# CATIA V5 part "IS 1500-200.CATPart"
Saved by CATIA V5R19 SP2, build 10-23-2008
Part number: IS 1500-200
Bounding box of the stored display mesh (mm): x -37.351 to 37.351, y -37.351 to 37.351, z 0 to 510
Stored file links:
  C:\Users\Bora\Desktop\3D Katı model\IS serisi\IS 1500\IS 1500-200.CATPart
  C:\Program Files\Dassault Systemes\B19\intel_a\reffiles\standard\MetricThickPitch.txt
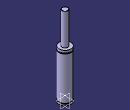
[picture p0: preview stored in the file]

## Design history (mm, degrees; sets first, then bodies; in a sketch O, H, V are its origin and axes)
Body1 (main body)
  Sketch1 on yz-plane, origin (0, 0, 0), H (0, 1, 0), V (0, 0, 1)
    point P1 (37.5, 291.5)
    point P2 (37.5, 286.5)
    point P5 (18, 509)
    point P7 (18, 509)
    point P12 (37.5, 286.5)
    point P13 (37.5, 291.5)
    arc A1 centre (37.5, 289) radius 2.5 from (37.5, 291.5) to (37.5, 286.5) ccw
    line L1 (37.5, 0) -> (37.5, 8)
    line L2 (18, 509) -> (18, 307)
    arc A2 centre (17, 509) radius 1 from (18, 509) to (17, 510) ccw
    line L3 (33.5, 13) -> (33.5, 8)
    line L4 (37.5, 13) -> (37.5, 286.5)
    line L5 (37.5, 291.5) -> (37.5, 307)
    line L6 (17, 510) -> (0, 510)
    point P15 (0, 510)
    line L7 (18, 307) -> (37.5, 307)
    line L8 (0, 0) -> (37.5, 0)
    line L9 (33.5, 8) -> (37.5, 8)
    line L10 (33.5, 13) -> (37.5, 13)
    coincidence: P15 V, P1 P13, P2 P12, P5 P7
    tangency: L6 A2
    horizontal: L7 H, L8 H, L9 H, L10 H
  Shaft1: profile Sketch1, axis Sketch1.V, angle 360
  Sketch2 on face of Shaft1 from Sketch1.L8, origin (0, 0, 0), H (1, 0, 0), V (0, -1, 0)
    point P1 (20, 0)
    distance P1 V = 20
  Hole1: placed by Sketch2, at (20, 0, 0) direction (0, 0, 1), diameter 6.647, depth 13, threaded "M8", thread diameter 8, thread depth 13, pitch 1.25
  CircPattern1: of Hole1, instances 4, angular step 90, axis from xy-plane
